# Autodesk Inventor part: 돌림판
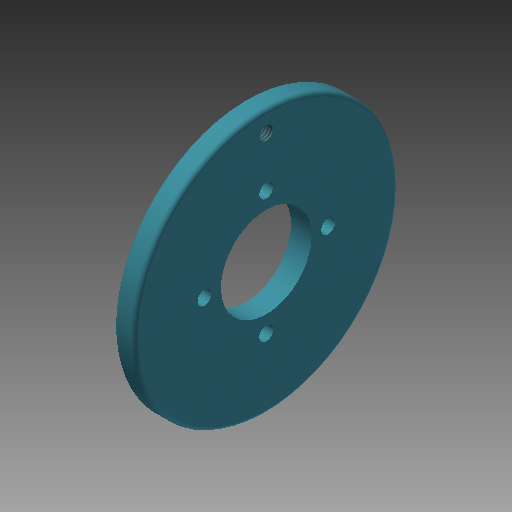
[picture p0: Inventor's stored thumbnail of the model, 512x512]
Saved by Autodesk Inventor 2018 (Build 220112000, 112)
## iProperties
Created: 2019-10
Part Number: 돌림판
Material: 스테인리스강
Document SubType Name: Modeling
Designer: mduedu
Density: 1 g/cm^3
Appearance: 커뎃 파란색
Author: mduedu
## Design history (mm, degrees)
sketch "스케치1" dims "d3" = 30
  geometry: C1 r 32 at (0, 0); C2 r 11 at (0, 0); C3 r 1.7 at (15, 0); C4 r 1.7 at (0, 15); C5 r 1.7 at (-15, 0); C6 r 1.7 at (0, -15); 2 further points
  constraints: 6 centre point, 3 coincident, 2 horizontal alignment, 11 other
  dimensions: "d0" = 64 diameter of C1; "d2" = 3.4 diameter of C3; "d4" = 22 diameter of C2; "d7" = 360 deg dimension on point (0, 0) C3.centre (derived)
extrude "돌출1" new body sketch "스케치1" distance "d9" = 5; taper "d10" = 0 deg
sketch "스케치2" dims "d11" = 54
  geometry: 3 further points
  constraints: 2 vertical alignment, 1 coincident, 2 other
hole "구멍1" sketch "스케치2" at (0, 27) diameter "d13" = 3.242; stored, may be unused: countersink angle "d17" = 90 deg, drill point angle "d19" = 118 deg; dims "d14" = 6, "d15" = 4, "d16" = 2, "d18" = 8
fillet "모깎기1" dims "d20" = 1
node "솔리드1"
